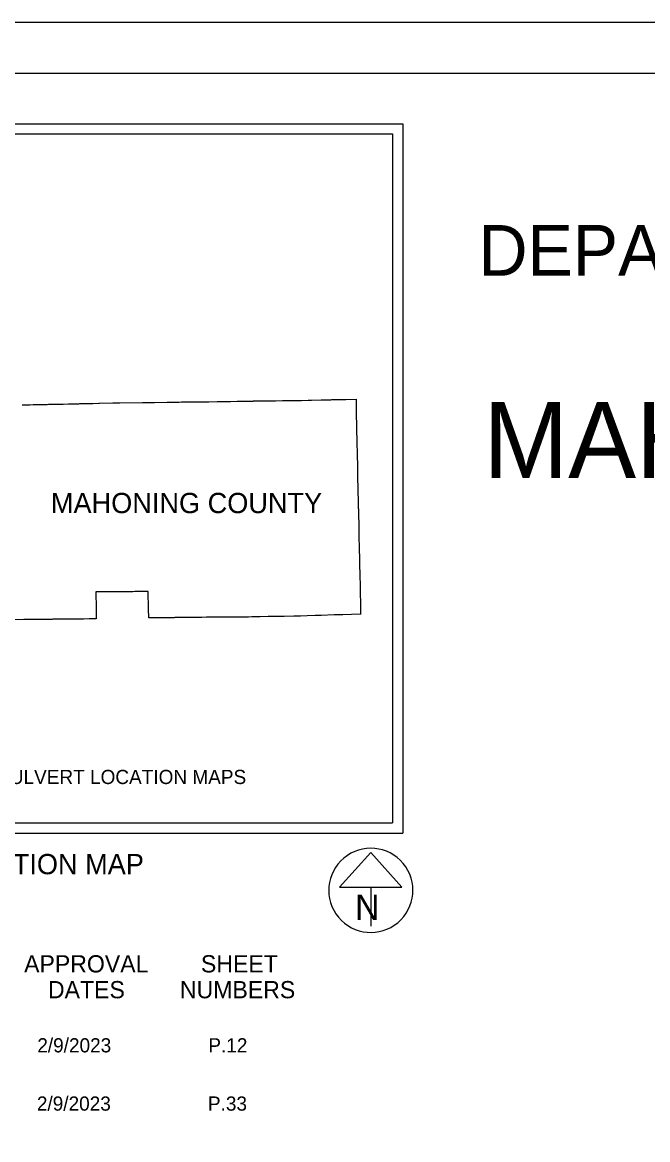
# Model space of a CAD drawing. Extents: x 0 to 34, y 0 to 22.
# Drawn here: x 5.25 to 11.41, y 10.97 to 22 of the extents above; entities that cross this region are included whole.
import ezdxf

# ---------------------------------------------------------------- set-up
doc = ezdxf.new("R2010")
doc.units = 0
for name, color, linetype in [('Default', 7, 'Continuous'), ('GM_X_County', 7, 'Continuous'), ('SH_Border', 7, 'Continuous'), ('SH_Cut_Line', 7, 'Continuous'), ('SH_Data', 7, 'Continuous'), ('SH_Text', 7, 'Continuous')]:
    doc.layers.add(name, color=color, linetype=linetype)

msp = doc.modelspace()

# ---------------------------------------------------------------- linework, layer by layer
at = {"layer": 'GM_X_County'}
msp.add_lwpolyline([(5.247, 18.226), (5.251, 18.226), (5.256, 18.226), (5.258, 18.226), (5.263, 18.226), (5.28, 18.227), (5.288, 18.227), (5.301, 18.227), (5.311, 18.227), (5.324, 18.227), (5.356, 18.228), (5.371, 18.228), (5.388, 18.228), (5.389, 18.228), (5.409, 18.229), (5.424, 18.229), (5.434, 18.229), (5.436, 18.229), (5.437, 18.229), (5.439, 18.229), (5.443, 18.229), (5.447, 18.229), (5.452, 18.229), (5.455, 18.23), (5.457, 18.23), (5.458, 18.23), (5.46, 18.23), (5.462, 18.23), (5.463, 18.23), (5.47, 18.23), (5.475, 18.23), (5.48, 18.23), (5.486, 18.23), (5.493, 18.23), (5.507, 18.231), (5.513, 18.231), (5.52, 18.231), (5.523, 18.231), (5.526, 18.231), (5.527, 18.231), (5.529, 18.231), (5.537, 18.231), (5.539, 18.231), (5.547, 18.232), (5.575, 18.232), (5.588, 18.232), (5.591, 18.232), (5.605, 18.233), (5.608, 18.233), (5.614, 18.233), (5.623, 18.233), (5.627, 18.233), (5.633, 18.233), (5.636, 18.233), (5.64, 18.234), (5.64, 18.234), (5.641, 18.234), (5.641, 18.233), (5.641, 18.233), (5.642, 18.233), (5.642, 18.233), (5.642, 18.233), (5.642, 18.234), (5.643, 18.234), (5.643, 18.234), (5.644, 18.234), (5.651, 18.234), (5.704, 18.235), (5.706, 18.235), (5.71, 18.235), (5.721, 18.235), (5.722, 18.235), (5.724, 18.235), (5.728, 18.236), (5.733, 18.236), (5.743, 18.236), (5.746, 18.236), (5.75, 18.236), (5.755, 18.236), (5.758, 18.236), (5.764, 18.236), (5.768, 18.236), (5.77, 18.236), (5.78, 18.237), (5.784, 18.237), (5.787, 18.237), (5.802, 18.237), (5.803, 18.237), (5.805, 18.237), (5.817, 18.238), (5.83, 18.238), (5.836, 18.238), (5.84, 18.238), (5.858, 18.238), (5.874, 18.239), (5.946, 18.24), (6.002, 18.242), (6.008, 18.242), (6.01, 18.242), (6.143, 18.244), (6.152, 18.244), (6.155, 18.244), (6.209, 18.245), (6.435, 18.248), (6.467, 18.249), (6.526, 18.249), (6.552, 18.25), (6.676, 18.251), (6.752, 18.253), (6.754, 18.253), (6.757, 18.253), (6.758, 18.253), (6.759, 18.253), (6.786, 18.253), (6.786, 18.253), (6.795, 18.253), (6.819, 18.254), (6.825, 18.254), (6.858, 18.254), (6.873, 18.254), (6.877, 18.255), (6.901, 18.255), (6.907, 18.255), (6.923, 18.255), (6.931, 18.255), (6.941, 18.255), (6.953, 18.256), (6.969, 18.256), (6.984, 18.256), (7.027, 18.257), (7.038, 18.256), (7.043, 18.257), (7.05, 18.257), (7.051, 18.257), (7.053, 18.257), (7.057, 18.257), (7.061, 18.257), (7.064, 18.257), (7.066, 18.257), (7.067, 18.257), (7.069, 18.257), (7.07, 18.257), (7.074, 18.257), (7.075, 18.257), (7.081, 18.257), (7.083, 18.257), (7.085, 18.257), (7.088, 18.257), (7.171, 18.258), (7.216, 18.259), (7.303, 18.26), (7.368, 18.261), (7.392, 18.262), (7.402, 18.262), (7.411, 18.262), (7.442, 18.262), (7.446, 18.263), (7.45, 18.263), (7.451, 18.263), (7.452, 18.263), (7.461, 18.263), (7.468, 18.262), (7.469, 18.263), (7.469, 18.263), (7.469, 18.263), (7.47, 18.263), (7.47, 18.263), (7.472, 18.263), (7.476, 18.263), (7.496, 18.263), (7.5, 18.263), (7.503, 18.263), (7.506, 18.263), (7.508, 18.263), (7.51, 18.263), (7.512, 18.263), (7.514, 18.263), (7.516, 18.263), (7.518, 18.263), (7.519, 18.263), (7.521, 18.263), (7.523, 18.263), (7.525, 18.263), (7.526, 18.264), (7.53, 18.264), (7.566, 18.264), (7.571, 18.264), (7.597, 18.264), (7.606, 18.265), (7.615, 18.265), (7.626, 18.265), (7.626, 18.265), (7.66, 18.265), (7.669, 18.265), (7.693, 18.266), (7.71, 18.266), (7.738, 18.266), (7.744, 18.266), (7.813, 18.267), (7.814, 18.267), (7.837, 18.267), (7.869, 18.268), (7.877, 18.268), (7.901, 18.268), (7.924, 18.269), (8.001, 18.27), (8.068, 18.272), (8.084, 18.272), (8.1, 18.273), (8.194, 18.274), (8.201, 18.275), (8.205, 18.275), (8.216, 18.275), (8.223, 18.275), (8.226, 18.275), (8.237, 18.275), (8.244, 18.275), (8.25, 18.276), (8.256, 18.276), (8.259, 18.276), (8.265, 18.276), (8.271, 18.276), (8.281, 18.276), (8.292, 18.276), (8.302, 18.277), (8.309, 18.277), (8.315, 18.277), (8.323, 18.277), (8.328, 18.277), (8.33, 18.277), (8.333, 18.277), (8.336, 18.277), (8.337, 18.277), (8.337, 18.277), (8.339, 18.277), (8.341, 18.277), (8.343, 18.277), (8.347, 18.277), (8.348, 18.277), (8.349, 18.277), (8.438, 18.279), (8.539, 18.282), (8.54, 18.169), (8.54, 18.156), (8.541, 18.125), (8.543, 18.027), (8.543, 18.017), (8.545, 17.955), (8.546, 17.893), (8.546, 17.884), (8.55, 17.712), (8.553, 17.642), (8.554, 17.626), (8.554, 17.543), (8.554, 17.543), (8.558, 17.366), (8.56, 17.286), (8.56, 17.285), (8.561, 17.207), (8.562, 17.197), (8.562, 17.165), (8.565, 17.021), (8.567, 16.955), (8.567, 16.952), (8.568, 16.918), (8.571, 16.824), (8.573, 16.691), (8.574, 16.642), (8.576, 16.557), (8.579, 16.425), (8.58, 16.352), (8.582, 16.286), (8.582, 16.259), (8.582, 16.258), (8.582, 16.258), (8.584, 16.168), (8.585, 16.16), (8.495, 16.156), (8.409, 16.154), (8.325, 16.152), (8.195, 16.148), (8.19, 16.148), (8.137, 16.146), (8.057, 16.144), (7.991, 16.142), (7.925, 16.141), (7.832, 16.138), (7.805, 16.138), (7.764, 16.137), (7.762, 16.137), (7.673, 16.136), (7.594, 16.135), (7.511, 16.133), (7.478, 16.132), (7.434, 16.132), (7.398, 16.132), (7.362, 16.131), (7.352, 16.131), (7.346, 16.131), (7.325, 16.131), (7.302, 16.131), (7.238, 16.13), (7.178, 16.13), (7.177, 16.13), (7.176, 16.13), (7.149, 16.129), (7.132, 16.129), (7.064, 16.129), (7.019, 16.128), (6.917, 16.127), (6.914, 16.127), (6.911, 16.127), (6.906, 16.127), (6.903, 16.127), (6.898, 16.127), (6.897, 16.127), (6.893, 16.127), (6.892, 16.127), (6.884, 16.127), (6.88, 16.127), (6.876, 16.127), (6.872, 16.127), (6.869, 16.127), (6.866, 16.127), (6.861, 16.127), (6.858, 16.127), (6.855, 16.127), (6.853, 16.127), (6.851, 16.127), (6.848, 16.127), (6.847, 16.127), (6.843, 16.127), (6.752, 16.126), (6.746, 16.125), (6.614, 16.124), (6.507, 16.123), (6.505, 16.123), (6.495, 16.123), (6.493, 16.214), (6.49, 16.384), (6.481, 16.384), (6.424, 16.384), (6.359, 16.383), (6.34, 16.382), (6.337, 16.382), (6.331, 16.382), (6.33, 16.382), (6.309, 16.382), (6.302, 16.382), (6.291, 16.381), (6.279, 16.381), (6.265, 16.382), (6.262, 16.382), (6.252, 16.382), (6.249, 16.382), (6.209, 16.382), (6.179, 16.382), (6.114, 16.381), (6.074, 16.38), (6.045, 16.38), (6.019, 16.379), (6.016, 16.379), (6.013, 16.379), (6.011, 16.379), (6.009, 16.38), (6.008, 16.38), (6.007, 16.379), (6.005, 16.379), (6.004, 16.379), (6.003, 16.379), (6.001, 16.379), (6, 16.379), (5.999, 16.379), (5.998, 16.38), (5.975, 16.379), (5.975, 16.348), (5.975, 16.346), (5.976, 16.253), (5.976, 16.246), (5.978, 16.154), (5.978, 16.114), (5.978, 16.113), (5.909, 16.113), (5.853, 16.112), (5.767, 16.111), (5.721, 16.11), (5.706, 16.11), (5.609, 16.11), (5.602, 16.11), (5.6, 16.11), (5.597, 16.11), (5.589, 16.11), (5.58, 16.11), (5.576, 16.11), (5.572, 16.11), (5.563, 16.11), (5.559, 16.11), (5.557, 16.11), (5.555, 16.11), (5.55, 16.11), (5.543, 16.109), (5.506, 16.108), (5.435, 16.107), (5.414, 16.107), (5.378, 16.108), (5.344, 16.107), (5.301, 16.107), (5.265, 16.106), (5.177, 16.104)], dxfattribs=at)
at = {"layer": 'SH_Border'}
msp.add_lwpolyline([(1.5, 21.5), (33.5, 21.5), (33.5, 0.5), (1.5, 0.5)], close=True, dxfattribs=at)
at = {"layer": 'SH_Cut_Line'}
msp.add_lwpolyline([(0, 0), (34, 0), (34, 22), (0, 22)], close=True, dxfattribs=at)
at = {"layer": 'SH_Data'}
for p, q in [((2, 21), (9, 21)), ((9, 21), (9, 14)), ((2.1, 20.9), (8.9, 20.9)), ((8.9, 20.9), (8.9, 14.1)), ((2.1, 14.1), (8.9, 14.1)), ((2, 14), (9, 14)), ((8.685, 13.809), (8.377, 13.468)), ((8.992, 13.468), (8.685, 13.809)), ((8.377, 13.468), (8.992, 13.468)), ((8.685, 13.468), (8.685, 13.081)), ((8.685, 13.435), (8.685, 13.435)), ((8.685, 13.435), (8.685, 13.435))]:
    msp.add_line(p, q, dxfattribs=at)
msp.add_arc((8.685, 13.435), 0.415, 129.7798, 129.7633, dxfattribs=at)

# ---------------------------------------------------------------- texts
at = {"layer": 'Default'}
for s, p in [('P.12', (7.083, 11.836)), ('P.33', (7.079, 11.261))]:
    msp.add_text(s, height=0.14, dxfattribs=at).set_placement(p)
at = {"layer": 'SH_Data'}
for s, height, p in [('N', 0.25, (8.529, 13.144)), ('APPROVAL', 0.17, (5.267, 12.625)), ('SHEET', 0.17, (7.01, 12.625)), ('DATES', 0.17, (5.502, 12.37)), ('NUMBERS', 0.17, (6.803, 12.37)), ('2/9/2023', 0.14, (5.397, 11.836)), ('2/9/2023', 0.14, (5.393, 11.261))]:
    msp.add_text(s, height=height, dxfattribs=at).set_placement(p)
at = {"layer": 'SH_Text'}
for s, height, p in [('DEPARTMENT OF TRANSPORTATION', 0.5, (9.747, 19.5)), ('MAH/POR-CULVERTS-FY2024', 0.75, (9.795, 17.505)), ('MAHONING COUNTY', 0.2, (5.531, 17.157)), ('SEE P.2 FOR CULVERT LOCATION MAPS', 0.14, (3.784, 14.484)), ('LOCATION MAP', 0.2, (4.427, 13.594))]:
    msp.add_text(s, height=height, dxfattribs=at).set_placement(p)

doc.saveas('drawing.dxf')
